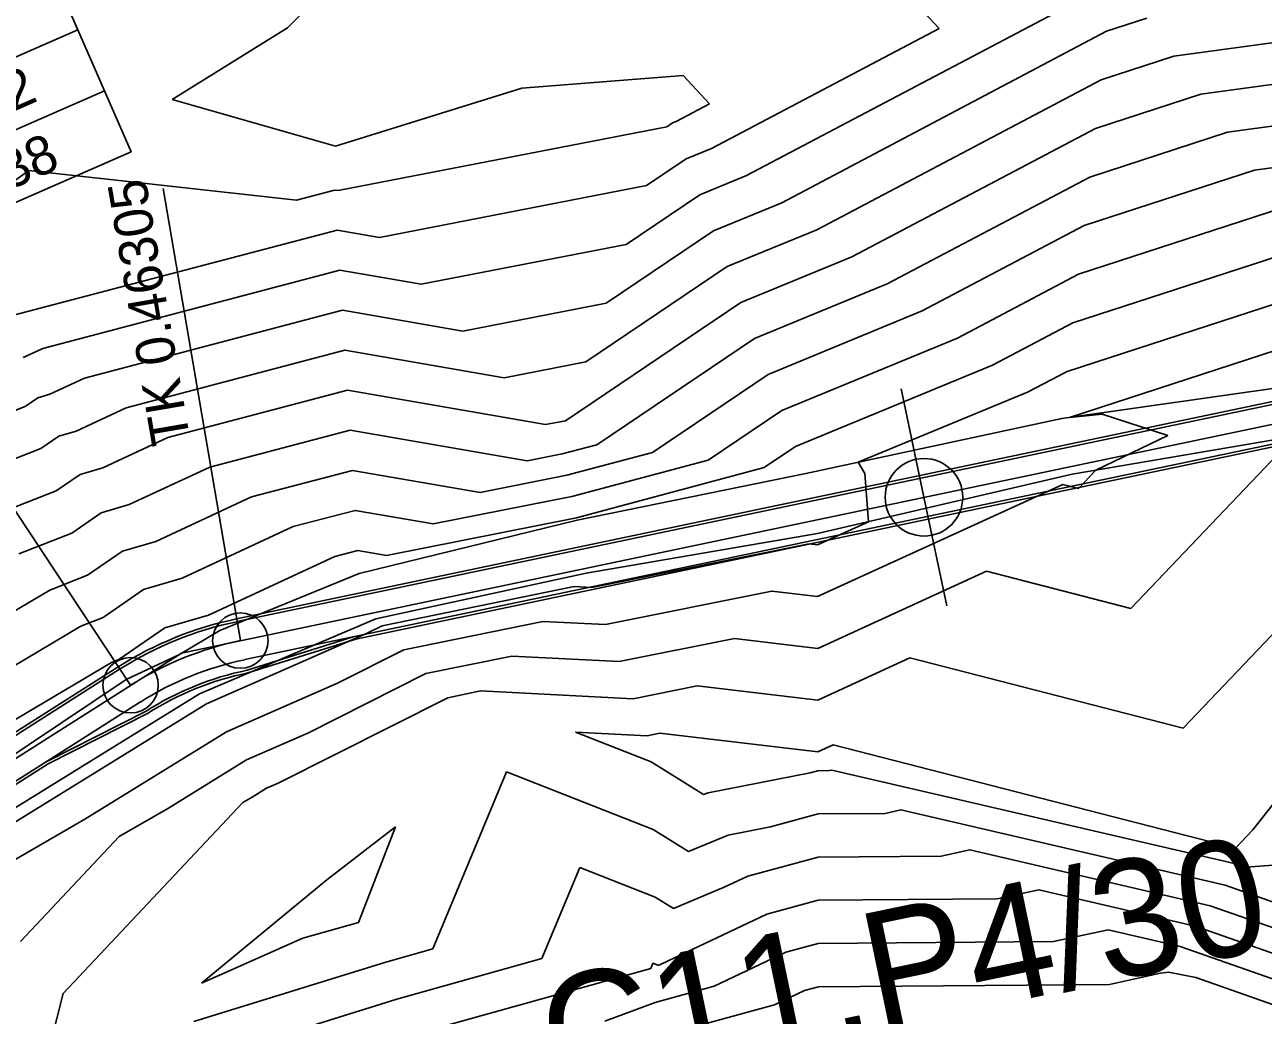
# Model space of a CAD drawing. Extents: x -549394 to -546608, y -1037055 to -1033629.
# Drawn here: x -548066.1 to -547954.3, y -1035601.5 to -1035512.1 of the extents above; entities that cross this region are included whole.
import ezdxf

# ---------------------------------------------------------------- set-up
doc = ezdxf.new("R2010")
doc.units = 0
for name, color, linetype in [('hlavni_vrst', 7, 'Continuous'), ('hrana_L', 7, 'Continuous'), ('norm_vrst', 7, 'Continuous'), ('POLYGONY_SITUACE_PO', 7, 'Continuous'), ('u_sirka_1_5m', 7, 'Continuous'), ('x_navrh_C11', 7, 'Continuous'), ('x_osa_C11', 7, 'Continuous'), ('x_popis_oblouky_C11', 7, 'Continuous'), ('x_popis_pricne_rezy_C11', 7, 'Continuous'), ('x_popis_velky_C11', 7, 'Continuous')]:
    doc.layers.add(name, color=color, linetype=linetype)

msp = doc.modelspace()

# ---------------------------------------------------------------- linework, layer by layer
at = {"layer": 'hlavni_vrst'}
for p, q in [((-548042.35, -1035512.4), (-548038.63, -1035508.58)), ((-548052.76, -1035518.87), (-548042.35, -1035512.4)), ((-547959.92, -1035518.38), (-547941.82, -1035515.91)), ((-548006.66, -1035516.7), (-548021.22, -1035517.83)), ((-548004.28, -1035519.26), (-548006.66, -1035516.7)), ((-548021.22, -1035517.83), (-548038.03, -1035523.08)), ((-547969.44, -1035521.47), (-547959.92, -1035518.38)), ((-548038.03, -1035523.08), (-548052.76, -1035518.87)), ((-548007.27, -1035520.84), (-548004.28, -1035519.26)), ((-548037.79, -1035527.08), (-548008.12, -1035521.32)), ((-548008.12, -1035521.32), (-548007.6, -1035520.97)), ((-548007.6, -1035520.97), (-548007.27, -1035520.84)), ((-547991.41, -1035533.05), (-547969.44, -1035521.47)), ((-548071.37, -1035529.32), (-548065.71, -1035525.26)), ((-548065.71, -1035525.26), (-548041.55, -1035527.93)), ((-548041.55, -1035527.93), (-548038.11, -1035527.03)), ((-548038.11, -1035527.03), (-548037.79, -1035527.08)), ((-548001.44, -1035537.19), (-547991.41, -1035533.05)), ((-547971.98, -1035543.39), (-547947.79, -1035535.53)), ((-548017.27, -1035547.84), (-548001.44, -1035537.19)), ((-547975.55, -1035545.27), (-547971.98, -1035543.39)), ((-548053.15, -1035549.36), (-548036.95, -1035545.09)), ((-548036.95, -1035545.09), (-548019.06, -1035548.19)), ((-547990.84, -1035551.58), (-547975.55, -1035545.27)), ((-548019.06, -1035548.19), (-548017.27, -1035547.84)), ((-548059.04, -1035552.09), (-548053.15, -1035549.36)), ((-547990.26, -1035552.61), (-547990.84, -1035551.58)), ((-548063.23, -1035554.17), (-548061.09, -1035552.69)), ((-548061.09, -1035552.69), (-548059.04, -1035552.09)), ((-547989.92, -1035556.95), (-547990.26, -1035552.61)), ((-548069.41, -1035556.58), (-548063.23, -1035554.17)), ((-547994.52, -1035559.05), (-547989.92, -1035556.95)), ((-548014.9, -1035562.89), (-547995.26, -1035558.96)), ((-547995.26, -1035558.96), (-547994.52, -1035559.05)), ((-548033.83, -1035566.34), (-548016.49, -1035562.81)), ((-548016.49, -1035562.81), (-548014.9, -1035562.89)), ((-548035.18, -1035567.02), (-548033.83, -1035566.34)), ((-548049.67, -1035573.38), (-548035.18, -1035567.02)), ((-548068.19, -1035584.8), (-548049.67, -1035573.38)), ((-547968.29, -1035593.77), (-547973.23, -1035594.84)), ((-547961.77, -1035595.29), (-547968.29, -1035593.77)), ((-547994.45, -1035595.01), (-547997.39, -1035595.8)), ((-547973.23, -1035594.84), (-547994.45, -1035595.01)), ((-547943.29, -1035601.77), (-547961.77, -1035595.29)), ((-547997.39, -1035595.8), (-548003.85, -1035598.87)), ((-548003.85, -1035598.87), (-548009.18, -1035600.33)), ((-548009.18, -1035600.33), (-548013.71, -1035602.03))]:
    msp.add_line(p, q, dxfattribs=at)
at = {"layer": 'hrana_L'}
for p, q in [((-547942.25, -1035543.35), (-547972.47, -1035547.64)), ((-547972.47, -1035547.64), (-547995.58, -1035552.59)), ((-547971.54, -1035552.66), (-547942.64, -1035547.74)), ((-547995.58, -1035552.59), (-548016.23, -1035556.8)), ((-547994.52, -1035558.02), (-547971.54, -1035552.66)), ((-548016.23, -1035556.8), (-548035.89, -1035561.64)), ((-548015.39, -1035561.59), (-547994.52, -1035558.02)), ((-548035.89, -1035561.64), (-548048.48, -1035566.77)), ((-548034.4, -1035565.71), (-548015.39, -1035561.59)), ((-548050.32, -1035572.47), (-548034.4, -1035565.71)), ((-548052.12, -1035568.92), (-548048.48, -1035566.77)), ((-548052.12, -1035568.92), (-548056.93, -1035571.19)), ((-548056.93, -1035571.19), (-548071.74, -1035581.11)), ((-548070.83, -1035585.15), (-548050.32, -1035572.47))]:
    msp.add_line(p, q, dxfattribs=at)
at = {"layer": 'norm_vrst'}
for p, q in [((-547983.55, -1035512.45), (-547991.06, -1035504.34)), ((-548000.93, -1035525.72), (-547967.91, -1035508.32)), ((-547968.42, -1035512.71), (-547964.78, -1035511.52)), ((-548004.1, -1035523.28), (-547983.55, -1035512.45)), ((-547997.75, -1035528.17), (-547968.42, -1035512.71)), ((-547962.35, -1035514.95), (-547941.76, -1035512.14)), ((-547968.93, -1035517.09), (-547962.35, -1035514.95)), ((-547994.58, -1035530.61), (-547968.93, -1035517.09)), ((-547957.5, -1035521.81), (-547941.88, -1035519.68)), ((-547969.94, -1035525.86), (-547957.5, -1035521.81)), ((-548006.37, -1035524.21), (-548004.1, -1035523.28)), ((-547955.07, -1035525.24), (-547941.94, -1035523.45)), ((-548009.95, -1035526.63), (-548006.37, -1035524.21)), ((-548005.13, -1035527.46), (-548000.93, -1035525.72)), ((-547988.24, -1035535.5), (-547969.94, -1035525.86)), ((-547970.45, -1035530.24), (-547955.07, -1035525.24)), ((-548034.05, -1035531.3), (-548009.95, -1035526.63)), ((-548011.78, -1035531.93), (-548005.13, -1035527.46)), ((-548003.9, -1035530.7), (-547997.75, -1035528.17)), ((-547970.96, -1035534.62), (-547952.64, -1035528.67)), ((-548068.23, -1035538.63), (-548037.88, -1035530.64)), ((-548037.88, -1035530.64), (-548034.05, -1035531.3)), ((-548013.61, -1035537.23), (-548003.9, -1035530.7)), ((-548002.67, -1035533.94), (-547994.58, -1035530.61)), ((-547985.06, -1035537.94), (-547970.45, -1035530.24)), ((-548030.3, -1035535.52), (-548011.78, -1035531.93)), ((-547971.47, -1035539), (-547950.21, -1035532.1)), ((-548015.44, -1035542.54), (-548002.67, -1035533.94)), ((-548064.46, -1035541.32), (-548037.65, -1035534.25)), ((-548037.65, -1035534.25), (-548030.3, -1035535.52)), ((-547981.89, -1035540.38), (-547970.96, -1035534.62)), ((-548000.2, -1035540.43), (-547988.24, -1035535.5)), ((-548026.55, -1035539.75), (-548013.61, -1035537.23)), ((-548060.69, -1035544), (-548037.41, -1035537.86)), ((-548037.41, -1035537.86), (-548026.55, -1035539.75)), ((-547998.97, -1035543.67), (-547985.06, -1035537.94)), ((-547978.72, -1035542.83), (-547971.47, -1035539)), ((-547971.78, -1035547.54), (-547945.36, -1035538.96)), ((-548014.44, -1035550.01), (-548000.2, -1035540.43)), ((-547997.74, -1035546.91), (-547981.89, -1035540.38)), ((-548066.21, -1035542.13), (-548064.46, -1035541.32)), ((-548056.92, -1035546.68), (-548037.18, -1035541.48)), ((-548037.18, -1035541.48), (-548022.81, -1035543.97)), ((-548022.81, -1035543.97), (-548015.44, -1035542.54)), ((-547996.5, -1035550.16), (-547978.72, -1035542.83)), ((-548063.82, -1035545.45), (-548060.69, -1035544)), ((-548009.41, -1035550.7), (-547998.97, -1035543.67)), ((-548066.05, -1035546.55), (-548064.91, -1035545.77)), ((-548064.91, -1035545.77), (-548063.82, -1035545.45)), ((-548074.99, -1035550.04), (-548066.05, -1035546.55)), ((-548061.43, -1035548.77), (-548056.92, -1035546.68)), ((-548004.38, -1035551.39), (-547997.74, -1035546.91)), ((-547968.82, -1035547.26), (-547971.78, -1035547.54)), ((-547962.89, -1035549.19), (-547968.82, -1035547.26)), ((-548064.64, -1035550.36), (-548063, -1035549.23)), ((-548063, -1035549.23), (-548061.43, -1035548.77)), ((-548049.38, -1035552.04), (-548036.72, -1035548.7)), ((-548036.72, -1035548.7), (-548020.74, -1035551.47)), ((-547969.39, -1035552.29), (-547962.89, -1035549.19)), ((-547966.24, -1035564.77), (-547951.44, -1035549.24)), ((-548072.2, -1035553.31), (-548064.64, -1035550.36)), ((-548020.74, -1035551.47), (-548017.57, -1035550.84)), ((-548017.57, -1035550.84), (-548014.44, -1035550.01)), ((-548017.14, -1035552.76), (-548009.41, -1035550.7)), ((-547999.35, -1035552.07), (-547996.5, -1035550.16)), ((-548016.71, -1035554.67), (-548004.38, -1035551.39)), ((-548056.65, -1035555.41), (-548049.38, -1035552.04)), ((-548045.62, -1035554.72), (-548036.49, -1035552.32)), ((-548036.49, -1035552.32), (-548024.97, -1035554.31)), ((-548024.97, -1035554.31), (-548017.14, -1035552.76)), ((-548016.28, -1035556.59), (-547999.35, -1035552.07)), ((-547970.97, -1035553.96), (-547969.39, -1035552.29)), ((-547994.51, -1035563.71), (-547972.37, -1035553.6)), ((-547972.37, -1035553.6), (-547970.97, -1035553.96)), ((-548054.26, -1035558.73), (-548045.62, -1035554.72)), ((-548029.2, -1035557.15), (-548016.71, -1035554.67)), ((-548061.82, -1035557.98), (-548059.17, -1035556.15)), ((-548059.17, -1035556.15), (-548056.65, -1035555.41)), ((-548041.85, -1035557.4), (-548036.26, -1035555.93)), ((-548036.26, -1035555.93), (-548029.2, -1035557.15)), ((-548051.87, -1035562.05), (-548041.85, -1035557.4)), ((-548033.44, -1035559.99), (-548016.28, -1035556.59)), ((-548066.62, -1035559.85), (-548061.82, -1035557.98)), ((-548060.41, -1035561.78), (-548057.26, -1035559.61)), ((-548057.26, -1035559.61), (-548054.26, -1035558.73)), ((-548038.08, -1035560.08), (-548036.02, -1035559.54)), ((-548036.02, -1035559.54), (-548033.44, -1035559.99)), ((-548049.48, -1035565.38), (-548038.08, -1035560.08)), ((-547961.52, -1035575.59), (-547946.89, -1035560.24)), ((-548063.83, -1035563.12), (-548060.41, -1035561.78)), ((-548055.35, -1035563.07), (-548051.87, -1035562.05)), ((-547994.5, -1035568.38), (-547979.28, -1035561.42)), ((-547979.28, -1035561.42), (-547966.24, -1035564.77)), ((-548075.04, -1035569.77), (-548063.83, -1035563.12)), ((-548059, -1035565.59), (-548055.35, -1035563.07)), ((-547955.22, -1035584.76), (-547937.68, -1035562.37)), ((-548013.66, -1035566.24), (-547998.64, -1035563.23)), ((-547998.64, -1035563.23), (-547994.51, -1035563.71)), ((-548053.44, -1035566.53), (-548049.48, -1035565.38)), ((-548073.82, -1035573.97), (-548061.03, -1035566.39)), ((-548061.03, -1035566.39), (-548059, -1035565.59)), ((-548057.59, -1035569.4), (-548053.44, -1035566.53)), ((-548031.85, -1035568.5), (-548019.3, -1035565.95)), ((-548019.3, -1035565.95), (-548013.66, -1035566.24)), ((-548012.41, -1035569.58), (-548002.01, -1035567.5)), ((-548002.01, -1035567.5), (-547994.5, -1035568.38)), ((-548037.86, -1035571.52), (-548031.85, -1035568.5)), ((-548072.6, -1035578.17), (-548058.24, -1035569.65)), ((-548058.24, -1035569.65), (-548057.59, -1035569.4)), ((-548029.87, -1035570.66), (-548022.11, -1035569.09)), ((-548022.11, -1035569.09), (-548012.41, -1035569.58)), ((-547994.49, -1035573.04), (-547986.19, -1035569.25)), ((-547986.19, -1035569.25), (-547961.52, -1035575.59)), ((-548040.53, -1035576.03), (-548029.87, -1035570.66)), ((-548047.86, -1035575.92), (-548037.86, -1035571.52)), ((-548011.16, -1035572.92), (-548005.38, -1035571.76)), ((-548005.38, -1035571.76), (-547994.49, -1035573.04)), ((-548043.21, -1035580.53), (-548027.9, -1035572.83)), ((-548027.9, -1035572.83), (-548024.93, -1035572.22)), ((-548024.93, -1035572.22), (-548011.16, -1035572.92)), ((-548060.65, -1035583.8), (-548047.86, -1035575.92)), ((-548046.05, -1035578.45), (-548040.53, -1035576.03)), ((-548016.37, -1035575.94), (-548009.91, -1035576.26)), ((-548009.55, -1035578.63), (-548016.37, -1035575.94)), ((-548009.91, -1035576.26), (-548008.76, -1035576.03)), ((-548008.76, -1035576.03), (-547994.48, -1035577.71)), ((-547994.48, -1035577.71), (-547993.1, -1035577.07)), ((-547993.1, -1035577.07), (-547956.79, -1035586.4)), ((-548053.11, -1035582.8), (-548046.05, -1035578.45)), ((-548004.8, -1035581.58), (-548009.55, -1035578.63)), ((-548022.58, -1035579.52), (-548029.24, -1035595.49)), ((-548009.36, -1035584.73), (-548022.58, -1035579.52)), ((-547995.19, -1035579.61), (-548004.39, -1035581.41)), ((-547994.48, -1035579.42), (-547995.19, -1035579.61)), ((-547993.47, -1035579.41), (-547994.48, -1035579.42)), ((-547993.23, -1035579.36), (-547993.47, -1035579.41)), ((-547956.38, -1035587.92), (-547993.23, -1035579.36)), ((-548045.56, -1035581.8), (-548044.25, -1035580.99)), ((-548044.25, -1035580.99), (-548043.21, -1035580.53)), ((-548046.4, -1035582.28), (-548045.56, -1035581.8)), ((-548004.39, -1035581.41), (-548004.8, -1035581.58)), ((-548062.6, -1035599.51), (-548046.4, -1035582.28)), ((-548057.55, -1035585.36), (-548053.11, -1035582.8)), ((-547994.47, -1035583.32), (-547998.76, -1035584.48)), ((-547988.41, -1035583.27), (-547994.47, -1035583.32)), ((-547987, -1035582.96), (-547988.41, -1035583.27)), ((-547957.73, -1035589.76), (-547987, -1035582.96)), ((-548068.71, -1035588.44), (-548060.65, -1035583.8)), ((-548066.45, -1035594.83), (-548057.55, -1035585.36)), ((-548038.82, -1035589.27), (-548032.62, -1035584.48)), ((-548032.62, -1035584.48), (-548035.94, -1035593.12)), ((-548006.16, -1035586.72), (-548009.36, -1035584.73)), ((-548002.58, -1035585.22), (-548006.16, -1035586.72)), ((-547998.76, -1035584.48), (-548002.58, -1035585.22)), ((-547956.79, -1035586.4), (-547955.22, -1035584.76)), ((-547980.76, -1035586.57), (-547983.35, -1035587.13)), ((-547959.08, -1035591.6), (-547980.76, -1035586.57)), ((-547932.68, -1035586.53), (-547955.84, -1035588.11)), ((-547994.47, -1035587.21), (-548000.81, -1035588.93)), ((-547983.35, -1035587.13), (-547994.47, -1035587.21)), ((-548015.97, -1035588.15), (-548019.4, -1035596.37)), ((-548009.17, -1035590.83), (-548015.97, -1035588.15)), ((-547955.84, -1035588.11), (-547956.38, -1035587.92)), ((-548050.13, -1035598.6), (-548038.82, -1035589.27)), ((-548002.95, -1035589.94), (-548007.52, -1035591.85)), ((-548000.81, -1035588.93), (-548002.95, -1035589.94)), ((-547952.71, -1035591.53), (-547957.73, -1035589.76)), ((-548007.52, -1035591.85), (-548009.17, -1035590.83)), ((-547994.46, -1035591.11), (-547999.1, -1035592.36)), ((-547978.29, -1035590.98), (-547994.46, -1035591.11)), ((-547974.53, -1035590.17), (-547978.29, -1035590.98)), ((-547960.42, -1035593.45), (-547974.53, -1035590.17)), ((-547949.57, -1035594.94), (-547959.08, -1035591.6)), ((-548035.94, -1035593.12), (-548040.98, -1035594.52)), ((-547999.1, -1035592.36), (-548008.63, -1035596.88)), ((-547946.43, -1035598.36), (-547960.42, -1035593.45)), ((-548040.98, -1035594.52), (-548050.13, -1035598.6)), ((-548029.24, -1035595.49), (-548033.48, -1035596.68)), ((-548033.48, -1035596.68), (-548050.81, -1035602.06)), ((-548019.4, -1035596.37), (-548032.49, -1035600.03)), ((-548009.56, -1035597.25), (-548031.5, -1035603.37)), ((-548009.37, -1035596.78), (-548009.56, -1035597.25)), ((-548008.98, -1035596.93), (-548009.37, -1035596.78)), ((-548008.89, -1035596.99), (-548008.98, -1035596.93)), ((-548008.63, -1035596.88), (-548008.89, -1035596.99)), ((-547963.56, -1035597.7), (-547968.17, -1035598.7)), ((-547962.83, -1035597.59), (-547963.56, -1035597.7)), ((-547960.36, -1035598.09), (-547962.83, -1035597.59)), ((-547994.44, -1035598.91), (-547995.69, -1035599.24)), ((-547968.17, -1035598.7), (-547994.44, -1035598.91)), ((-547940.15, -1035605.19), (-547960.36, -1035598.09)), ((-548064.91, -1035608.46), (-548062.6, -1035599.51)), ((-548032.49, -1035600.03), (-548053.86, -1035606.67)), ((-547995.69, -1035599.24), (-547998.41, -1035600.53)), ((-547998.41, -1035600.53), (-548009.41, -1035603.56))]:
    msp.add_line(p, q, dxfattribs=at)
at = {"layer": 'POLYGONY_SITUACE_PO'}
for centre in [(-548046.62, -1035567.68), (-548056.53, -1035571.71)]:
    msp.add_circle(centre, 2.5, dxfattribs=at)
at = {"layer": 'u_sirka_1_5m'}
msp.add_circle((-547984.91, -1035554.75), 3.5, dxfattribs=at)
at = {"layer": 'x_navrh_C11'}
for p, q in [((-547935.9, -1035542.7), (-548046.92, -1035565.96)), ((-547935.18, -1035546.12), (-548046.21, -1035569.4)), ((-548046.01, -1035570.35), (-548036.42, -1035567.35)), ((-548045.95, -1035570.59), (-548036.2, -1035567.54)), ((-548057.52, -1035570.27), (-548106.46, -1035601.35)), ((-548055.64, -1035573.22), (-548104.59, -1035604.3)), ((-548055.12, -1035574.04), (-548064.08, -1035578.58)), ((-548055, -1035574.26), (-548063.96, -1035578.8))]:
    msp.add_line(p, q, dxfattribs=at)
for points in [[(-547935.95, -1035542.45), (-548046.97, -1035565.71)], [(-547944.92, -1035548.42), (-548036.2, -1035567.54)], [(-548057.65, -1035570.06), (-548091.33, -1035591.44)], [(-548063.96, -1035578.8), (-548104.45, -1035604.51)]]:
    msp.add_lwpolyline(points, dxfattribs=at)
for radius, start, end in [(32, 101.6573, 122.4137), (31.75, 101.6573, 122.4137), (28.25, 101.6573, 122.4137), (27.28, 101.6573, 122.4137), (27.03, 101.6309, 122.4393)]:
    msp.add_arc((-548040.5, -1035597.07), radius, start, end, dxfattribs=at)
at = {"layer": 'x_osa_C11'}
msp.add_lwpolyline([(-547913.49, -1035539.79), (-548051.94, -1035568.8), (-548118.03, -1035610.76)], dxfattribs=at)
msp.add_arc((-548040.46, -1035597.04), 30, 101.8343, 122.4137, dxfattribs=at)
at = {"layer": 'x_popis_oblouky_C11'}
for points in [[(-548091.18, -1035519.11), (-548063.7, -1035507.09), (-548061.3, -1035512.58), (-548088.78, -1035524.61)], [(-548088.78, -1035524.61), (-548061.3, -1035512.58), (-548058.89, -1035518.08), (-548086.37, -1035530.11)], [(-548086.37, -1035530.11), (-548058.89, -1035518.08), (-548056.48, -1035523.58), (-548083.97, -1035535.6)]]:
    msp.add_lwpolyline(points, close=True, dxfattribs=at)
for points in [[(-548046.61, -1035567.68), (-548053.6, -1035526.9)], [(-548056.53, -1035571.71), (-548079.38, -1035537.22)]]:
    msp.add_lwpolyline(points, dxfattribs=at)
at = {"layer": 'x_popis_pricne_rezy_C11'}
msp.add_lwpolyline([(-547982.86, -1035564.54), (-547984.91, -1035554.75), (-547986.96, -1035544.97)], dxfattribs=at)

# ---------------------------------------------------------------- texts
at = {"layer": 'x_popis_oblouky_C11'}
for s, rotation, p in [('y=0.482', 23.6574, (-548080.14, -1035525.68)), ('t=5.438', 23.6574, (-548077.16, -1035531.31)), ('TK 0.46305', 99.7197, (-548051.11, -1035549.69))]:
    msp.add_text(s, height=3.5, rotation=rotation, dxfattribs=at).set_placement(p)
at = {"layer": 'x_popis_velky_C11'}
msp.add_text('C11,P4/30', height=10.5, rotation=11.7515, dxfattribs=at).set_placement((-548018.21, -1035608.87))

doc.saveas('drawing.dxf')
